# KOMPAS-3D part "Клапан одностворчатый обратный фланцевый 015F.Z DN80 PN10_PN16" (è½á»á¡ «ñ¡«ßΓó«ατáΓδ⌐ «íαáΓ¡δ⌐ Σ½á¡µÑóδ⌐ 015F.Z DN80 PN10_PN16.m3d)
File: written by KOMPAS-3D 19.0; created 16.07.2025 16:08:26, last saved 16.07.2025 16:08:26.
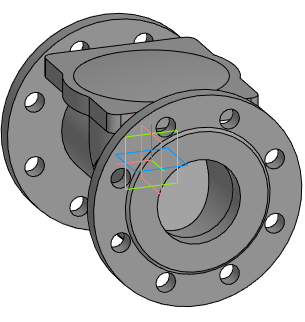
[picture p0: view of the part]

Document properties: Полное имя файла: E:\Dendor Работа Сачек\3D для проектировщиков\5.4 Тип 015F.Z. Клапан одностворчатый обратный фланцевый\stp_Клапан одностворчатый обратный фланцевый 015F.Z PN10_16\Клапан одностворчатый обратный фланцевый 015F.Z DN80 PN10_PN16.m3d

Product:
- Part/product: Клапан одностворчатый обратный фланцевый 015F.Z DN80 PN10_PN16

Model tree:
1. Операция без истории:1
2. Операция без истории:2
